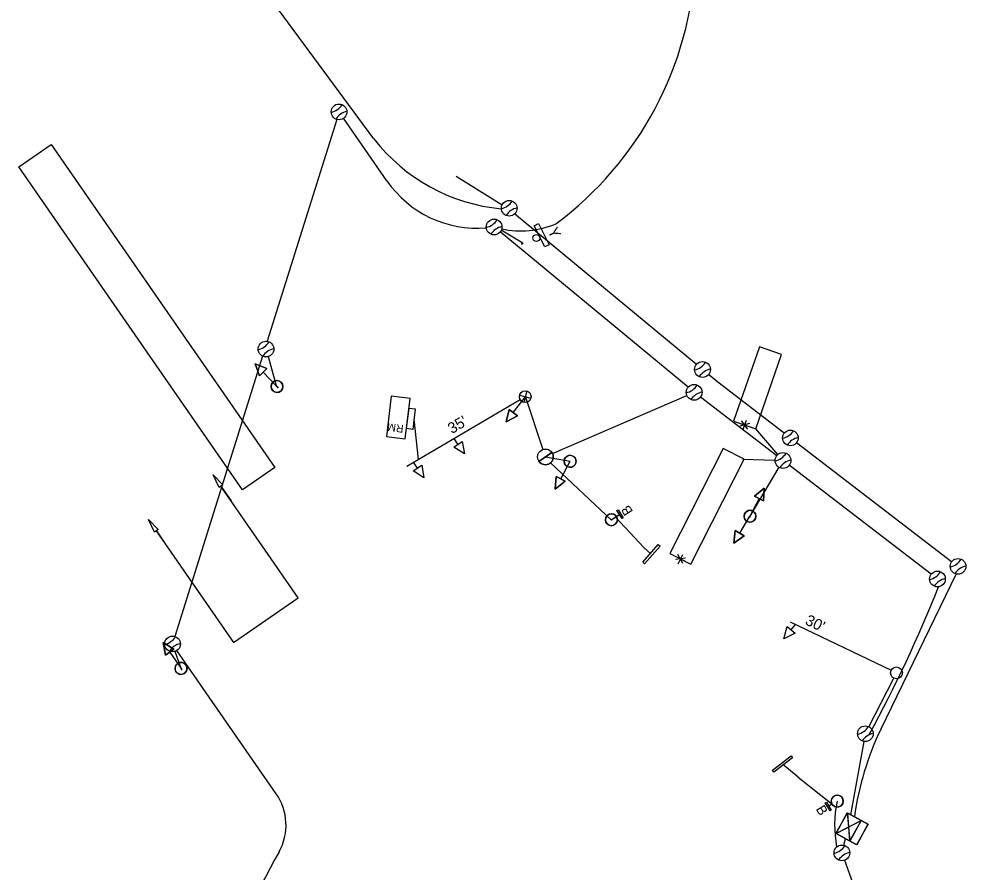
# Model space of a CAD drawing. Extents: x 596176 to 605330, y 332416 to 402398.
# Drawn here: x 602314.8 to 602556.7, y 357121.7 to 357338.9 of the extents above; entities that cross this region are included whole.
import ezdxf

# ---------------------------------------------------------------- set-up
doc = ezdxf.new("R2010")
doc.units = 0
for name, color, linetype in [('P_LTG', 7, 'Continuous'), ('P_MISC_TXT', 7, 'Continuous'), ('P_SIG', 7, 'Continuous'), ('P_SIG_Bold', 7, 'Continuous'), ('P_SIG_Conduit', 7, 'Continuous'), ('P_SIG_IC', 7, 'Continuous'), ('P_SIG_Loops', 7, 'Continuous')]:
    doc.layers.add(name, color=color, linetype=linetype)

# ---------------------------------------------------------------- blocks, each defined once
blk = doc.blocks.new('_U333')
at = {"layer": 'P_SIG_Loops'}
for p, q in [((0.06, -0.08), (-0.05, 0.08)), ((-0.05, -0.08), (0.05, 0.08)), ((0, 0), (0, -0.23)), ((-0.1, 0), (0.1, 0))]:
    blk.add_line(p, q, dxfattribs=at)
blk.add_lwpolyline([(0, -0.23), (1.14, -0.23), (1.14, 0.23), (0, 0.23)], close=True, dxfattribs=at)
blk = doc.blocks.new('_U318')
at = {"layer": 'P_SIG'}
blk.add_line((-0.02, -0.02), (-0.97, -0.02), dxfattribs=at)
blk.add_lwpolyline([(-0.91, 0.02), (-0.97, -0.02), (-0.91, -0.06)], dxfattribs=at)
for centre, start, end in [((-1.16, 0.78), 270, 287.76231), ((-1.16, -0.82), 72.23768, 90)]:
    blk.add_arc(centre, 0.799, start, end, dxfattribs=at)
blk = doc.blocks.new('_U225')
at = {"layer": 'P_SIG'}
blk.add_circle((0, 0.01), 6.1, dxfattribs=at)
for centre, start, end in [((-15.46, 0.12), 336.67411, 22.52722), ((15.45, 0.15), 157.57508, 203.4282)]:
    blk.add_arc(centre, 13.28, start, end, dxfattribs=at)
blk = doc.blocks.new('CONTROL CABINET_7')
at = {"layer": 'P_SIG'}
for p, q in [((-0.229, 0.305), (0.229, 0.305)), ((-0.229, -0.152), (-0.229, 0.305)), ((0.229, 0.305), (0.229, -0.152)), ((-0.229, 0.152), (0.229, 0.152)), ((-0.229, -0.152), (0.229, 0.152)), ((0.229, -0.152), (-0.229, 0.152)), ((0.229, -0.152), (-0.229, -0.152))]:
    blk.add_line(p, q, dxfattribs=at)

msp = doc.modelspace()

# ---------------------------------------------------------------- linework, layer by layer
at = {"layer": 'P_SIG'}
for p, q in [((602445.97, 357286.23), (602447.03, 357286.78)), ((602448.68, 357280.88), (602445.97, 357286.23)), ((602447.03, 357286.78), (602449.75, 357281.42)), ((602449.75, 357281.42), (602448.68, 357280.88)), ((602376.95, 357248.96), (602380.46, 357245.31)), ((602440.64, 357238.66), (602443.71, 357242.68)), ((602416.48, 357226.73), (602415.35, 357237)), ((602426.55, 357230.6), (602425.57, 357232.08)), ((602447.17, 357226.25), (602450.47, 357228.51)), ((602416.21, 357224.52), (602415.23, 357226)), ((602452.72, 357221.8), (602455.11, 357226.26)), ((602503.21, 357216.76), (602500.9, 357212.26)), ((602465.58, 357211.36), (602467.68, 357212.71)), ((602473.85, 357204.28), (602466.63, 357212.04)), ((602498.28, 357207.94), (602500.9, 357212.26)), ((602473.85, 357204.28), (602475.65, 357202.7)), ((602511.39, 357183.35), (602512.51, 357184.73)), ((602353.15, 357177.66), (602356.03, 357173.5)), ((602513.18, 357145.82), (602509.3, 357149.05)), ((602513.18, 357145.82), (602521.81, 357138.93)), ((602521.83, 357138.94), (602520.98, 357138.42)), ((602522.8, 357131.45), (602525.66, 357136.72)), ((602525.66, 357136.72), (602530.93, 357133.86)), ((602525.66, 357136.72), (602526.32, 357129.54)), ((602522.8, 357131.45), (602529.17, 357134.82)), ((602529.17, 357134.82), (602526.32, 357129.54)), ((602530.93, 357133.86), (602528.07, 357128.59)), ((602528.07, 357128.59), (602522.8, 357131.45))]:
    msp.add_line(p, q, dxfattribs=at)
for points in [[(602445.97, 357286.23), (602447.03, 357286.78), (602449.75, 357281.42), (602448.68, 357280.88)], [(602409.55, 357242.82), (602408.31, 357232.55), (602413.1, 357231.98), (602414.33, 357242.25)], [(602415.03, 357234.38), (602413.45, 357234.58), (602414.08, 357239.81), (602415.66, 357239.62)], [(602428.19, 357228.14), (602425.45, 357229.87), (602427.65, 357231.33)], [(602417.84, 357222.06), (602415.11, 357223.79), (602417.3, 357225.25)], [(602468.33, 357211.7), (602467.03, 357213.72), (602467.31, 357213.9), (602468.61, 357211.88)], [(602473.59, 357200.57), (602477.56, 357205.07), (602478.01, 357204.67), (602474.04, 357200.17)], [(602509.51, 357181.06), (602510.37, 357184.19), (602512.41, 357182.52)], [(602511.72, 357150.75), (602506.96, 357147.09), (602506.6, 357147.57), (602511.36, 357151.22)], [(602520.35, 357139.44), (602521.6, 357137.39), (602521.33, 357137.22), (602520.07, 357139.27)]]:
    msp.add_lwpolyline(points, close=True, dxfattribs=at)
for points in [[(602374.9, 357251.09), (602377.9, 357249.87), (602376, 357248.04), (602374.9, 357251.09)], [(602377.9, 357249.87), (602374.9, 357251.09), (602376, 357248.04), (602377.9, 357249.87)], [(602438.85, 357236.3), (602439.59, 357239.45), (602441.69, 357237.86), (602438.85, 357236.3)], [(602438.85, 357236.3), (602439.59, 357239.45), (602441.69, 357237.86), (602438.85, 357236.3)], [(602439.59, 357239.45), (602438.85, 357236.3), (602441.69, 357237.86), (602439.59, 357239.45)], [(602450.47, 357228.51), (602447.17, 357226.25)], [(602451.32, 357219.19), (602451.55, 357222.42), (602453.88, 357221.18), (602451.32, 357219.19)], [(602451.55, 357222.42), (602451.32, 357219.19), (602453.88, 357221.18), (602451.55, 357222.42)], [(602504.55, 357219.4), (602504.38, 357216.17), (602502.03, 357217.36), (602504.55, 357219.4)], [(602504.38, 357216.17), (602504.55, 357219.4), (602502.03, 357217.36), (602504.38, 357216.17)], [(602496.75, 357205.4), (602497.15, 357208.62), (602499.41, 357207.26), (602496.75, 357205.4)], [(602496.75, 357205.4), (602497.15, 357208.62), (602499.41, 357207.26), (602496.75, 357205.4)], [(602497.15, 357208.62), (602496.75, 357205.4), (602499.41, 357207.26), (602497.15, 357208.62)], [(602351.46, 357180.09), (602354.23, 357178.41), (602352.07, 357176.9), (602351.46, 357180.09)], [(602354.23, 357178.41), (602351.46, 357180.09), (602352.07, 357176.9), (602354.23, 357178.41)]]:
    msp.add_lwpolyline(points, dxfattribs=at)
for centre, radius in [((602396.26, 357315.24), 2), ((602435.75, 357285.93), 2), ((602446.53, 357283.14), 0.9), ((602377.66, 357254.84), 2), ((602380.46, 357245.31), 1.52), ((602380.46, 357245.31), 1.52), ((602380.46, 357245.31), 1.52), ((602486.68, 357243.82), 2), ((602448.82, 357227.38), 2), ((602455.11, 357226.26), 1.52), ((602455.11, 357226.26), 1.52), ((602455.11, 357226.26), 1.52), ((602509.3, 357226.46), 2), ((602500.9, 357212.26), 1.52), ((602500.9, 357212.26), 1.52), ((602500.9, 357212.26), 1.52), ((602465.61, 357211.38), 1.52), ((602548.63, 357196.29), 2), ((602353.86, 357179.74), 2), ((602356.03, 357173.5), 1.52), ((602356.03, 357173.5), 1.52), ((602356.03, 357173.5), 1.52), ((602530.28, 357156.89), 2), ((602523.11, 357139.72), 1.52), ((602524.29, 357126.54), 2)]:
    msp.add_circle(centre, radius, dxfattribs=at)
for centre, radius, start, end in [((602393.33, 357319.39), 4.36, 282.2572, 328.1103), ((602399.11, 357311.05), 4.36, 101.3562, 147.2093), ((602432.82, 357290.08), 4.36, 282.2572, 328.1103), ((602438.6, 357281.74), 4.36, 101.3562, 147.2093), ((602374.74, 357258.98), 4.36, 282.2572, 328.1103), ((602380.51, 357250.65), 4.36, 101.3562, 147.2093), ((602380.46, 357245.31), 1.52, 313.9518, 133.9518), ((602380.46, 357245.31), 1.52, 133.9518, 313.9518), ((602483.75, 357247.97), 4.36, 282.2572, 328.1103), ((602489.53, 357239.63), 4.36, 101.3562, 147.2093), ((602448.82, 357227.38), 2, 304.6821, 34.3829), ((602455.11, 357226.26), 1.52, 61.9575, 241.9575), ((602455.11, 357226.26), 1.52, 241.9575, 61.9575), ((602506.38, 357230.61), 4.36, 282.2572, 328.1103), ((602448.82, 357227.38), 2, 214.3829, 304.6821), ((602512.15, 357222.27), 4.36, 101.3562, 147.2093), ((602500.9, 357212.26), 1.52, 63.0248, 243.0248), ((602500.9, 357212.26), 1.52, 243.0248, 63.0248), ((602465.61, 357211.38), 1.52, 67.1809, 247.1809), ((602465.61, 357211.38), 1.52, 247.1809, 67.1809), ((602545.71, 357200.43), 4.36, 282.2572, 328.1103), ((602551.49, 357192.1), 4.36, 101.3562, 147.2093), ((602350.94, 357183.89), 4.36, 282.2572, 328.1103), ((602356.72, 357175.55), 4.36, 101.3562, 147.2093), ((602356.03, 357173.5), 1.52, 124.7799, 304.7799), ((602356.03, 357173.5), 1.52, 304.7799, 124.7799), ((602527.36, 357161.04), 4.36, 282.2572, 328.1103), ((602533.14, 357152.7), 4.36, 101.3562, 147.2093), ((602523.11, 357139.72), 1.52, 39.6959, 219.6959), ((602523.11, 357139.72), 1.52, 219.6959, 39.6959), ((602521.37, 357130.68), 4.36, 282.2572, 328.1103), ((602527.14, 357122.35), 4.36, 101.3562, 147.2093)]:
    msp.add_arc(centre, radius, start, end, dxfattribs=at)
at = {"layer": 'P_SIG_Bold'}
for p, q in [((602442.22, 357243.1), (602445.13, 357242.34)), ((602444.05, 357244.17), (602443.3, 357241.27)), ((602413.5, 357224.98), (602442.38, 357241.96)), ((602511.15, 357185.38), (602536.84, 357173.03))]:
    msp.add_line(p, q, dxfattribs=at)
for centre in [(602443.67, 357242.72), (602538.19, 357172.38)]:
    msp.add_circle(centre, 1.5, dxfattribs=at)
at = {"layer": 'P_SIG_Conduit'}
for p, q in [((602395.66, 357313.34), (602377.97, 357256.81)), ((602485.14, 357245.1), (602437.29, 357284.66)), ((602443.05, 357281.79), (602437.57, 357285.12)), ((602376.79, 357253.03), (602354.46, 357181.65)), ((602378.2, 357252.91), (602380.35, 357245.23)), ((602443.66, 357242.83), (602448.19, 357229.28)), ((602450.63, 357228.23), (602484.84, 357243.03)), ((602507.71, 357227.68), (602488.26, 357242.61)), ((602448.83, 357227.39), (602455.11, 357226.26)), ((602465.66, 357211.3), (602450.14, 357225.88)), ((602547.05, 357197.5), (602510.89, 357225.25)), ((602508.28, 357224.74), (602500.9, 357212.26)), ((602356.03, 357173.5), (602354.51, 357177.85)), ((602531.19, 357158.67), (602537.52, 357171.04)), ((602526.55, 357136.24), (602529.93, 357154.92)), ((602524.79, 357128.47), (602525.22, 357130.14))]:
    msp.add_line(p, q, dxfattribs=at)
for points in [[(602408.46, 357297.68), (602397.42, 357313.62)], [(602380.27, 357141.58), (602355, 357178.1)], [(602524.96, 357124.65), (602542.53, 357075.51)]]:
    msp.add_lwpolyline(points, dxfattribs=at)
for centre, radius, start, end in [((602398.62, 357357.71), 88.5, 306.6886, 357.2473), ((602431.48, 357313.61), 28, 214.6821, 274.6677), ((602442.49, 357308.37), 23.43, 258.1678, 292.6114), ((602211.9, 357329.17), 363, 331.6225, 338.1903), ((602368.76, 357133.62), 14, 331.0197, 34.6821), ((602551.61, 357133.52), 29.17, 167.7207, 190.845), ((602786.9, 356902.02), 464, 151.0197, 155.7252)]:
    msp.add_arc(centre, radius, start, end, dxfattribs=at)
at = {"layer": 'P_SIG_IC'}
for points in [[(602405.14, 357308.41), (602379.59, 357343.03)], [(602437.77, 357291.52), (602426.06, 357298.75)], [(602487.27, 357250.91), (602440.97, 357289.25)], [(602509.6, 357233.42), (602492.7, 357246.41), (602490.35, 357248.36)], [(602552.24, 357200.64), (602512.77, 357230.98)], [(602534.26, 357158.15), (602553.51, 357197.67)]]:
    msp.add_lwpolyline(points, dxfattribs=at)
for centre, radius, start, end in [((602441.83, 357336.7), 46.33, 217.6309, 264.6908), ((602601.6, 357125.63), 74.78, 154.2191, 172.2395)]:
    msp.add_arc(centre, radius, start, end, dxfattribs=at)
at = {"layer": 'P_SIG_Loops'}
for p, q in [((602500.8, 357235.86), (602498.28, 357235.22)), ((602500.33, 357234.48), (602498.75, 357236.53)), ((602499.09, 357234.22), (602499.97, 357236.75)), ((602499.53, 357235.53), (602502.36, 357234.54)), ((602508, 357227.98), (602502.36, 357234.54)), ((602499.07, 357226.81), (602507.3, 357226.53)), ((602484.49, 357201.56), (602481.9, 357201.27)), ((602483.84, 357200.26), (602482.54, 357202.5)), ((602482.58, 357200.17), (602483.79, 357202.56)), ((602483.18, 357201.4), (602485.86, 357200.05))]:
    msp.add_line(p, q, dxfattribs=at)
for points in [[(602314.77, 357301.26), (602322.99, 357306.95), (602379.9, 357224.72), (602371.67, 357219.03), (602314.77, 357301.26)], [(602349.71, 357208.59), (602369.42, 357180.11), (602385.86, 357191.49), (602366.17, 357219.95)], [(602366.19, 357219.93), (602368.8, 357216.15)], [(602349.74, 357208.55), (602352.35, 357204.77)]]:
    msp.add_lwpolyline(points, dxfattribs=at)
for points in [[(602502.36, 357234.54), (602508.95, 357253.42), (602503.28, 357255.4), (602496.7, 357236.51)], [(602485.86, 357200.05), (602499.44, 357226.8), (602494.09, 357229.51), (602480.51, 357202.76)], [(602365.71, 357219.6), (602364.19, 357222.81), (602366.67, 357220.26)], [(602349.26, 357208.22), (602347.75, 357211.43), (602350.22, 357208.88)]]:
    msp.add_lwpolyline(points, close=True, dxfattribs=at)

# ---------------------------------------------------------------- block references
at = {"layer": 'P_LTG', "xscale": 0.32808333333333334}
for name, p, yscale, rotation in [('_U333', (602443.07, 357281.77), 0.3280833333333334, -155.84643614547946), ('_U318', (602380.46, 357245.31), 0.3280833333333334, 124.68212460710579), ('_U318', (602500.9, 357212.26), 0.32808333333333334, 62.435578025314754), ('_U333', (602356.03, 357173.5), 0.3280833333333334, -55.31787539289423)]:
    msp.add_blockref(name, p, dxfattribs=dict(at, yscale=yscale, rotation=rotation))
at = {"layer": 'P_MISC_TXT', "xscale": 13.123333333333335, "yscale": 13.123333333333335, "rotation": -118.98465916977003}
msp.add_blockref('CONTROL CABINET_7', (602525.99, 357133.13), dxfattribs=at)
at = {"layer": 'P_SIG', "xscale": 13.123333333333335, "yscale": 13.123333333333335, "rotation": -119.0529008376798}
msp.add_blockref('CONTROL CABINET_7', (602525.99, 357133.13), dxfattribs=at)
at = {"layer": 'P_SIG_IC', "xscale": 0.3280833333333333, "yscale": 0.32808333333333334, "rotation": 124.5442935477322}
for p in [(602439.59, 357290.7), (602488.81, 357249.64), (602511.19, 357232.21), (602553.88, 357199.5)]:
    msp.add_blockref('_U225', p, dxfattribs=at)

# ---------------------------------------------------------------- texts
at = {"layer": 'P_SIG'}
for s, height, rotation, p in [('Y', 2.8, 296.8728, (602449.26, 357284.95)), ('RM', 2, 173.1428, (602412.79, 357235.5)), ('B', 2.52, 122.7164, (602471.21, 357213.47)), ('B', 2.52, 301.5335, (602517.57, 357137.71))]:
    msp.add_text(s, height=height, rotation=rotation, dxfattribs=at).set_placement(p)
at = {"layer": 'P_SIG_Bold'}
for s, rotation, p in [("35'", 30.4459, (602424.99, 357233.15)), ("30'", 334.3347, (602514.72, 357184.84))]:
    msp.add_text(s, height=2.8, rotation=rotation, dxfattribs=at).set_placement(p)

doc.saveas('drawing.dxf')
